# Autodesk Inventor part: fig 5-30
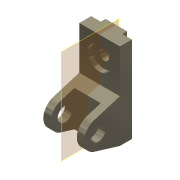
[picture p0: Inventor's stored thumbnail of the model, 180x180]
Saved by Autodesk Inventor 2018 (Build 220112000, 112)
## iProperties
Shininess: 65.0
Angle Display Precision: 2
Document Length Units: 11269
Document Angle Units: 11279
Document Time Units: 11290
Document Mass Units: 11283
Document Length Units Precision: 3
Document Angle Units Precision: 2
Created: 2001-11
Part Number: fig 5-30
Document SubType Name: Modeling
Designer: Renu Muthoo
Density: 1 g/cm^3
Material: Generic
Appearance: Metal-Titanium (Polished)
Density: 0.0
Volumn: 0.0
Area: 0.0
PropertySet Name: Model Information
Control State: 0
Master: False
Checked Out: False
Author: Renu Muthoo
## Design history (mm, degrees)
node "Sketch1"
sketch "Sketch2"
  geometry: L1 (33.257, 104.664)-(33.257, -75.336); L2 (33.257, -75.336)-(8.257, -75.336); L3 (8.257, -75.336)-(-45.451, -59.045); L4 (-45.451, -1.628)-(8.257, 14.664); L5 (8.257, 14.664)-(8.257, 104.664); L6 (8.257, 104.664)-(33.257, 104.664); C1 r 15 at (-36.743, -30.336); A1 r 30 centre (-36.743, -30.336) between (-45.451, -1.628) and (-45.451, -59.045)
  constraints: 12 end point, 2 centre point, 2 equal length, 2 parallel, 2 point on circle, 2 tangent, 1 coincident, 1 perpendicular, 1 vertical
  dimensions: "d0" = 180 distance of L1.start L1.end; "d1" = 30 radius of A1; "d2" = 25 distance of L5.end L1.start; "d3" = 45 distance from line of L2 A1.centre; "d4" = 70 distance from line of L1 A1.centre; "d5" = 30 diameter of C1
extrude "Extrusion1" new body sketch "Sketch2" distance "d6" = 85; taper "d7" = 0 deg
workplane "Work Plane1"
sketch "Sketch3"
  geometry: L1 (15, 62.364)-(70, 62.364); L2 (70, 62.364)-(70, -52.386); L3 (70, -52.386)-(15, -52.386); L4 (15, -52.386)-(15, 62.364); L5 (0, -45)-(0, -28.708) reference
  constraints: 8 end point, 2 parallel, 1 horizontal, 1 perpendicular
  dimensions: "d8" = 55 distance of L1.start L1.end; "d9" = 15 distance between parallel lines of L5 L4
extrude "Extrusion2" cut sketch "Sketch3" distance "d10" = 50; taper "d11" = 0 deg
sketch "Sketch4"
  geometry: L1 (0, 25)-(85, 25) reference; L2 (0, 0)-(0, 25) reference; L3 (20, 25)-(65, 25); L4 (65, 25)-(65, 35); L5 (65, 35)-(20, 35); L6 (20, 35)-(20, 25)
  constraints: 8 end point, 2 parallel, 1 horizontal, 1 perpendicular, 1 point on line
  dimensions: "d12" = 45 distance of L4.end L5.end; "d13" = 10 distance of L3.end L4.end; "d14" = 20 distance between parallel lines of L2 L6
extrude "Extrusion3" join sketch "Sketch4" stored distance "d15" = 50; taper "d16" = 0 deg
sketch "Sketch5"
  geometry: L1 (85, 0)-(85, 90) reference; L2 (0, 90)-(85, 90) reference; 1 further point
  dimensions: "d17" = 42 distance from line of L2 point (42.5, 48); "d18" = 42.5 distance from line of L1 point (42.5, 48)
hole "Hole1" sketch "Sketch5" at (42.5, 48) diameter "d19" = 20; stored, may be unused: countersink angle "d23" = 82 deg, drill point angle "d25" = 118 deg; dims "d20" = 6, "d21" = 50, "d22" = 10, "d24" = 8
workplane "Work Plane5"
body "Solid1"
